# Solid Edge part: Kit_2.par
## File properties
Sűrűség: 0,000 kg/m^3
Pontosság: 0,990
Author: ahadarics
Last saved by: psaghy
Revision: 78
Username: ahadarics
Dokumentum tartalom típus: 0
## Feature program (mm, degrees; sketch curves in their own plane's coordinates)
base feature "unnamed BaseFeature 1"
sketch for "Furat_1" plane through (0, 0, 41.5) normal (0, 0, 1) x-axis (-0.707107, -0.707107, 0)
  hole centre (-39.9515, 0) bore radius 3.3235
hole "Furat_1" nominal diameter 8 finite  VBottomAngle = 118 deg
sketch for "unnamed Hole 1" plane through (0, 0, 41.5) normal (0, 0, 1) x-axis (-0.707107, -0.707107, 0)
  hole centre (0, 39.9515) bore radius 3.3235
hole "unnamed Hole 1" finite
sketch for "unnamed Hole 2" plane through (0, 0, 41.5) normal (0, 0, 1) x-axis (-0.707107, -0.707107, 0)
  hole centre (39.9515, 0) bore radius 3.3235
hole "unnamed Hole 2" finite
sketch for "unnamed Hole 3" plane through (0, 0, 41.5) normal (0, 0, 1) x-axis (-0.707107, -0.707107, 0)
  hole centre (0, -39.9515) bore radius 3.3235
hole "unnamed Hole 3" finite
pattern "unnamed Pattern 1" of "Furat_1", "unnamed Hole 1", "unnamed Hole 2", "unnamed Hole 3"
sketch for "Furat_5" plane through (37.5, 0.0062, 22.7488) normal (1, 0, 0) x-axis (0, 0, -1)
  hole centre (-2.7512, 7.4938) bore radius 7.475
hole "Furat_5" nominal diameter 16.662 finite  ThreadDepth = 17 mm
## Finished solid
Body 1: solid body, 521 faces, 1211 edges, 754 vertices, 8 internal voids.
  Faces by surface: cylinder 204, plane 147, cone 54, torus 48, sphere 37, spline 27, swept 4
  Edges by curve: curve on surface 471, circle 397, line 331, spline 12
Bounding box of the edges (mm; curved faces can reach further): 75.001 x 75.000 x 59.500, from (-37.5, -37.5, 8) to (37.5009, 37.5, 67.5).
Cylindrical faces by radius (mm): R0.3049 x1, R0.3063 x2, R0.3073 x1, R0.3094 x1, R0.3138 x1, R0.3275 x1, R0.3358 x1, R0.3579 x2, R0.3595 x2, R0.3746 x2, R0.3825 x2, R0.3862 x2, R0.3932 x1, R0.395 x1, R0.3966 x1, R0.3998 x2, R0.4022 x1, R0.4063 x1, R0.4065 x1, R0.4073 x2, R0.4133 x1, R0.4335 x2, R0.4417 x1, R0.4627 x2, R0.4813 x1, R0.4994 x1, R0.5 x3, R0.5003 x1, R0.5051 x1, R0.5233 x1, R0.5325 x1, R0.5327 x1, R0.5437 x2, R0.5682 x1, R0.5785 x2, R0.6044 x1, R0.6048 x2, R0.6079 x1, R0.6085 x1, R0.6126 x1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
Conical faces (half-angle, radius in mm at the cone's reference point): 1 deg R23.75 x4, 1 deg R28 x4, 1.6538 deg R11.75 x1, 3.5477 deg R12.7454 x1, 5.762 deg R10.4 x1, 11.1239 deg R10.0056 x1, 15 deg R20.3906 x1, 15.3654 deg R10.7214 x1, 19.3654 deg R11.1921 x1, 25.0169 deg R14.31 x1, 30 deg R5.1443 x1, 30 deg R11.8557 x2, 30 deg R12.1443 x1, 30 deg R21.75 x1, 32.8285 deg R32.5 x1, 37.7468 deg R27.2199 x3, 37.7468 deg R33.5 x3, 45 deg R2.75 x1, 45 deg R2.825 x1, 45 deg R4.3 x8, 45 deg R6.35 x8, 45 deg R7.47 x1, 45 deg R10.15 x2, 45 deg R15.25 x1, 59 deg R3.3235 x4
Toroidal faces (ring radius, tube radius in mm): R0.5012 r0.5005 x1, R1 r0.5 x1, R1.0357 r0.4999 x1, R4.3 r0.3 x4, R4.7 r0.3 x1, R6.45 r0.2 x4, R7.15 r0.5 x4, R10.25 r1 x2, R10.3 r0.3 x1, R10.3085 r0.3 x1, R11.4279 r0.25 x1, R12 r0.5 x1, R12.2464 r0.5 x1, R14.8 r0.2 x1, R19 r2 x1, R19.3663 r0.5 x1, R23 r0.5 x1, R24.6454 r1 x1, R24.7327 r1 x3, R25.9494 r1 x3, R27.0059 r1 x3, R27.0694 r1 x1, R34 r1 x3, R38.0449 r1 x1, R38.5 r1 x6
Spherical faces by radius (mm): R1 x37
Planar faces by outward normal: +x 22, +y 8, +z 31, -x 2, -y 7, -z 19, oblique 58
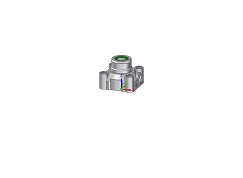
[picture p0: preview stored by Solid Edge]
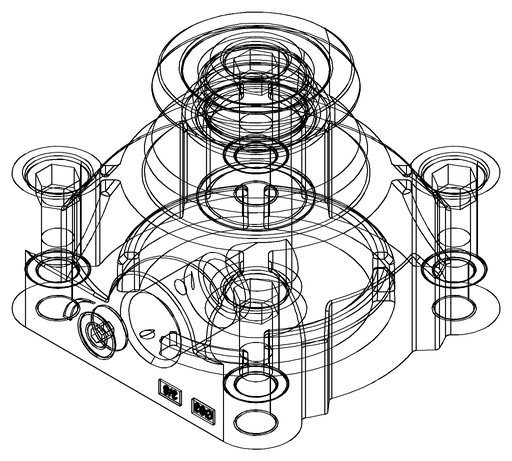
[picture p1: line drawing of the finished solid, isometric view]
